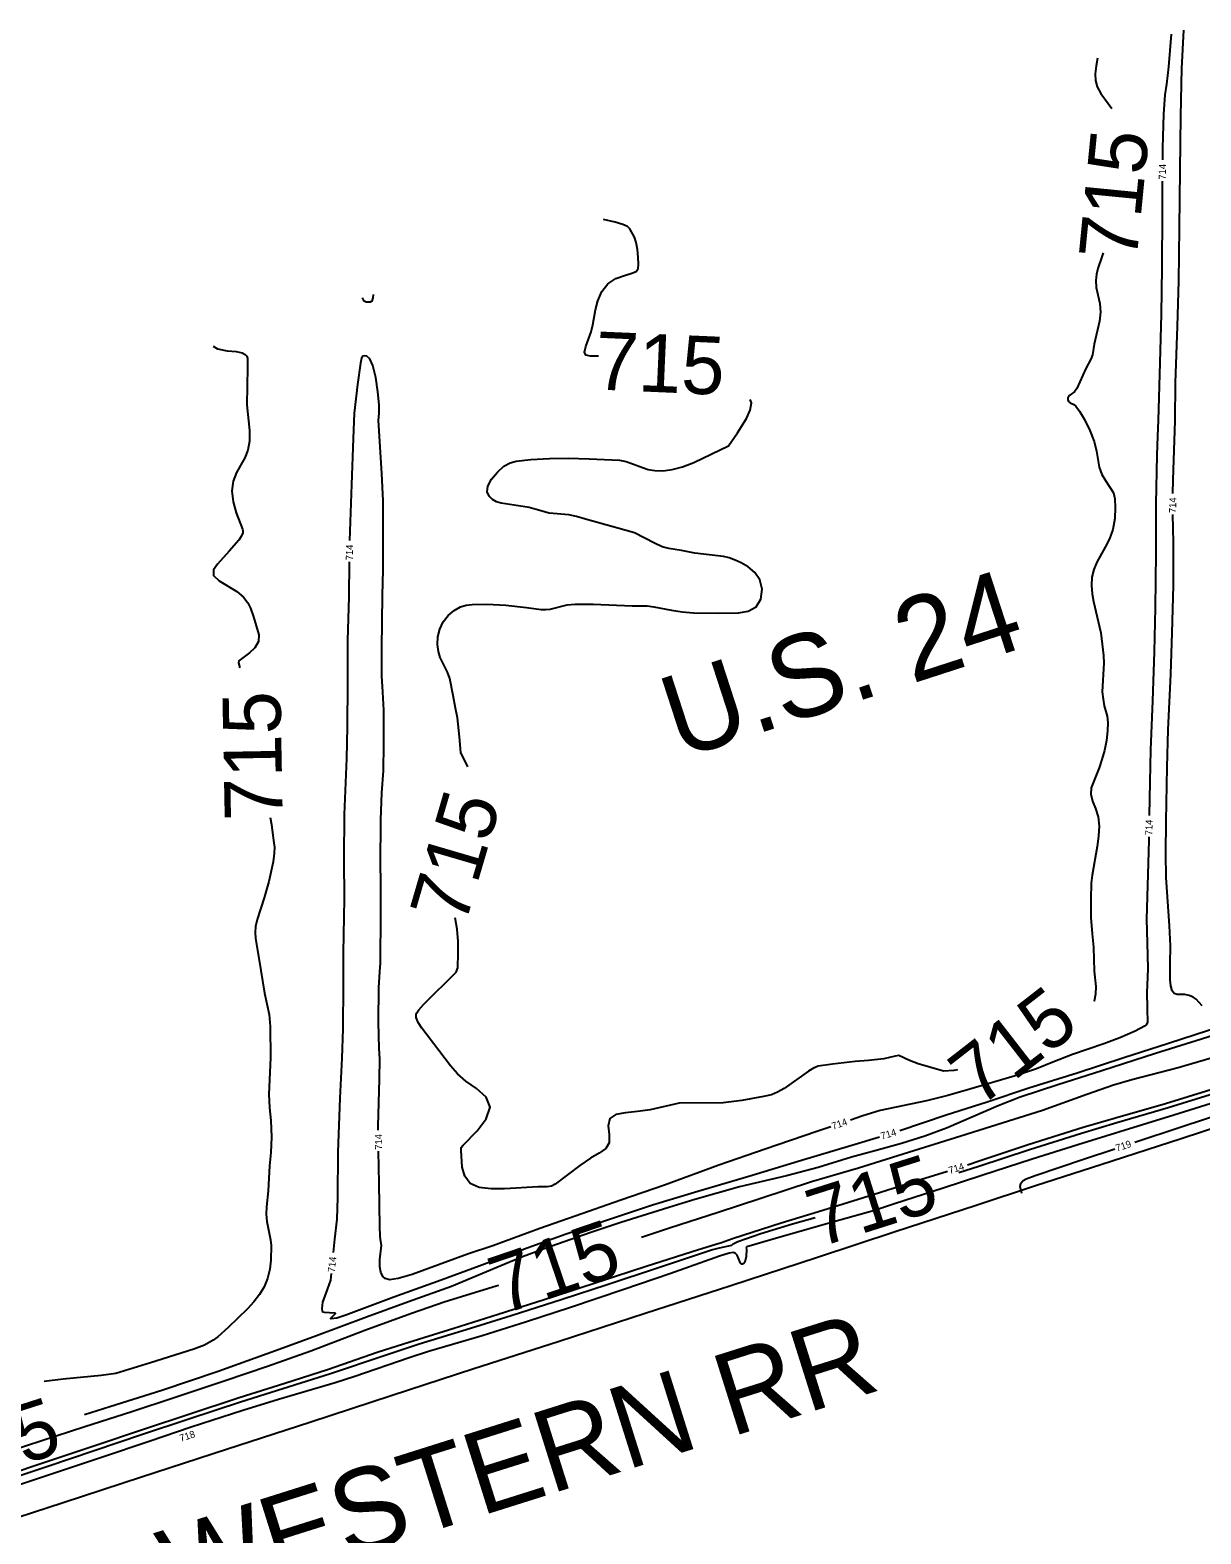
# Model space of a CAD drawing. Extents: x -468563856 to 36492962, y -306094093 to 11899197.
# Drawn here: x 1823055 to 1823721, y 531405 to 532260 of the extents above; entities that cross this region are included whole.
import ezdxf

# ---------------------------------------------------------------- set-up
doc = ezdxf.new("R2010")
doc.units = 0
for name, color, linetype in [('DT_X_Contour_Minor', 7, 'Continuous'), ('Level 14', 7, 'Continuous'), ('Level 19', 7, 'Continuous'), ('Level 40', 7, 'Continuous')]:
    doc.layers.add(name, color=color, linetype=linetype)

msp = doc.modelspace()

# ---------------------------------------------------------------- linework, layer by layer
at = {"layer": 'DT_X_Contour_Minor'}
for points in [[(1823704.79, 531997), (1823704.91, 532004.75), (1823706.02, 532038.27), (1823706.35, 532059.86), (1823707.51, 532092.13), (1823708.22, 532117.68), (1823708.55, 532147.93), (1823708.95, 532180.69), (1823709.28, 532211.54), (1823709.87, 532238.63), (1823711.02, 532260.42)], [(1823703.81, 532258.07), (1823702.34, 532239.45), (1823701.12, 532229.67), (1823700.23, 532223.63), (1823699.47, 532212.53), (1823698.89, 532193.45), (1823698.85, 532186.6)], [(1823661.94, 532244.38), (1823661.11, 532240.06), (1823660.62, 532235.61), (1823660.77, 532231.7), (1823661.75, 532228.09), (1823663.75, 532224.44), (1823670.18, 532215.81)], [(1823698.79, 532174.6), (1823698.77, 532172.19), (1823698.7, 532156.44), (1823698.5, 532125.16), (1823698.23, 532098.84), (1823697.46, 532071.21), (1823696.47, 532038.45), (1823696.13, 532029.55), (1823695.62, 532018.79), (1823695.08, 531991.07), (1823695.03, 531963.09), (1823694.75, 531931.89), (1823694.14, 531906.93), (1823693.2, 531879.13), (1823692.02, 531851.22), (1823691.64, 531832.98), (1823691.33, 531813.8)], [(1823378.07, 532074.94), (1823373.55, 532074.95), (1823371, 532075.63), (1823370.17, 532077.38), (1823370.85, 532080.52), (1823373.88, 532088.84), (1823374.88, 532092.86), (1823376.4, 532101.37), (1823377.8, 532106.55), (1823380.06, 532111.77), (1823383.47, 532116.17), (1823388.08, 532119.13), (1823393, 532120.93), (1823397.1, 532122.12), (1823399.56, 532123.22), (1823400.62, 532124.78), (1823400.85, 532127.35), (1823400.71, 532131.22), (1823400.29, 532135.68), (1823399.59, 532139.74), (1823398.64, 532142.67), (1823395.91, 532147.45), (1823394.63, 532148.72), (1823392.03, 532149.94), (1823387.57, 532151.13), (1823380.95, 532152.63)], [(1823665.16, 532133.78), (1823664.45, 532131.41), (1823662.11, 532124.84), (1823661.31, 532121.57), (1823660.96, 532118.05), (1823661.23, 532114.13), (1823663.18, 532104.95), (1823663.66, 532099.99), (1823663.13, 532095.01), (1823660.1, 532081.91), (1823659.03, 532075.76), (1823658.06, 532073.37), (1823655.21, 532067.93), (1823650.23, 532056.69), (1823648.76, 532054.81), (1823645.54, 532052.46), (1823645.04, 532051.37), (1823645.02, 532050.26), (1823645.53, 532049.3), (1823646.41, 532048.53), (1823648.39, 532047.58), (1823649.66, 532046.5), (1823651.62, 532043.83), (1823654.45, 532039.01), (1823657.53, 532032.84), (1823660.02, 532026.52), (1823661.35, 532020.96), (1823662.86, 532011.82), (1823664.4, 532007.81), (1823666.4, 532004.27), (1823671.02, 531997.25), (1823671.72, 531994), (1823672.03, 531988.93), (1823671.77, 531982.75), (1823670.72, 531976.52), (1823668.77, 531971.09), (1823666.28, 531966.38), (1823661.49, 531957.96), (1823659.8, 531953.79), (1823658.8, 531949.39), (1823658.56, 531944.67), (1823658.93, 531939.91), (1823659.68, 531935.46), (1823663.76, 531917.65), (1823665.32, 531904.88), (1823665.47, 531900.53), (1823664.64, 531884.2), (1823665.07, 531880.01), (1823665.76, 531876.29), (1823667.4, 531870.29), (1823667.82, 531866.7), (1823667.66, 531861.94), (1823666.97, 531856.44), (1823665.88, 531850.84), (1823664.49, 531845.69), (1823662.9, 531841.05), (1823658.33, 531829.53), (1823658.11, 531825.92), (1823659.13, 531822.07), (1823660.79, 531817.84), (1823662.23, 531813.1), (1823662.8, 531807.79), (1823662.56, 531802.1), (1823661.8, 531796.26), (1823658.82, 531779.96), (1823658.35, 531775.39), (1823658.14, 531766.33), (1823658.2, 531755.83), (1823658.86, 531746.66), (1823659.73, 531738.96), (1823660.11, 531725.35), (1823660.96, 531716.55), (1823660.86, 531712.34), (1823659.97, 531708.26), (1823659.9, 531708.08)], [(1823249.99, 532110.14), (1823249.78, 532108.25), (1823249.15, 532106.35), (1823248.28, 532105.66), (1823246.01, 532105.66), (1823244.83, 532106.32), (1823243.88, 532108.12), (1823243.88, 532108.16)], [(1823159.02, 532080.63), (1823161.48, 532079.17), (1823166.96, 532078.09), (1823172, 532077.59), (1823175.38, 532076.92), (1823177.27, 532076), (1823178.17, 532074.95), (1823178.53, 532073.73), (1823178.48, 532068.54), (1823178.12, 532047.3), (1823179.67, 532032.81), (1823179.66, 532026.77), (1823178.7, 532021.65), (1823176.94, 532017.25), (1823172.26, 532008.8), (1823170.31, 532004.01), (1823169.51, 531998.47), (1823170.28, 531992.13), (1823172, 531985.9), (1823175.58, 531976.61), (1823175.94, 531975.68), (1823175.82, 531974.66), (1823174.87, 531972.5), (1823173.49, 531970.46), (1823168.17, 531964.07), (1823161.37, 531956.83), (1823159.11, 531953.46), (1823159.21, 531950.27), (1823162.39, 531947.24), (1823172.49, 531941.19), (1823176.26, 531937.97), (1823178.7, 531934.77), (1823180.2, 531931.81), (1823181.83, 531926.73), (1823184.98, 531916.55), (1823184.73, 531912.7), (1823182.72, 531909.21), (1823179.72, 531906.29), (1823173.52, 531901.71), (1823173.46, 531900.65), (1823174.14, 531897.76)], [(1823252.9, 531635.02), (1823252.86, 531637.27), (1823253.52, 531664.04), (1823253.72, 531675.56), (1823253.32, 531681.32), (1823253.01, 531696.4), (1823253.19, 531715.84), (1823253.77, 531725.23), (1823254.14, 531729.88), (1823254.34, 531758.33), (1823254.26, 531776.84), (1823254.09, 531785.39), (1823254.33, 531811.44), (1823254.81, 531826.78), (1823255.82, 531839.18), (1823256.03, 531854.42), (1823255.99, 531873.76), (1823255.56, 531884.07), (1823254.89, 531893.23), (1823254.81, 531908.99), (1823255.19, 531938.86), (1823255.74, 531953.6), (1823255.7, 531982.74), (1823255.69, 531992.8), (1823254.88, 532008.39), (1823253, 532038.41), (1823253.48, 532042.65), (1823253.34, 532047.37), (1823252.63, 532054.67), (1823251.41, 532062.87), (1823249.83, 532069.72), (1823248.05, 532073.55), (1823246.32, 532074.98), (1823244.91, 532075.2), (1823244.01, 532075.06), (1823243.4, 532073.97), (1823242.79, 532071.01), (1823241.06, 532058.95), (1823239.26, 532042.66), (1823238.59, 532028.26), (1823237.68, 532002.08), (1823236.57, 531970.18)], [(1823303.81, 531841.54), (1823299.93, 531849.76), (1823299.13, 531858.6), (1823297.95, 531869.38), (1823296.86, 531874.97), (1823295.52, 531882.04), (1823293.56, 531891.75), (1823292.29, 531895.31), (1823288.11, 531903.7), (1823287.06, 531907.15), (1823286.55, 531911.08), (1823286.79, 531915.43), (1823287.87, 531919.88), (1823289.84, 531924.06), (1823292.69, 531927.66), (1823296.07, 531930.5), (1823299.57, 531932.47), (1823302.91, 531933.52), (1823306.31, 531933.91), (1823314.68, 531933.98), (1823325.52, 531933.51), (1823337.12, 531932.06), (1823345.45, 531930.96), (1823348.12, 531930.92), (1823350.55, 531931.27), (1823360.29, 531933.6), (1823364.79, 531934.01), (1823375.19, 531934), (1823397.27, 531933.16), (1823405.9, 531933), (1823409.64, 531932.51), (1823419.67, 531930.57), (1823425.71, 531929.68), (1823432.12, 531929.18), (1823446.62, 531928.98), (1823457.73, 531929.11), (1823463.16, 531930.02), (1823467.78, 531932.48), (1823470.48, 531936.95), (1823471.15, 531942.5), (1823469.92, 531947.88), (1823467.05, 531952.1), (1823463.23, 531955.19), (1823459.27, 531957.45), (1823455.78, 531959.11), (1823452.54, 531960.29), (1823449.15, 531961.04), (1823432.83, 531962.94), (1823425.3, 531964.57), (1823418.19, 531965.6), (1823414.28, 531966.7), (1823409.94, 531968.61), (1823398.58, 531974.62), (1823389.12, 531977.19), (1823370.66, 531982.35), (1823365.68, 531983.77), (1823361.28, 531984.75), (1823350.02, 531985.84), (1823342.75, 531987.82), (1823338.77, 531988.89), (1823330.12, 531990.3), (1823322.86, 531991.39), (1823320.14, 531992.2), (1823317.84, 531993.46), (1823315.9, 531995.33), (1823314.79, 531997.89), (1823315.12, 532001.19), (1823317.25, 532005.14), (1823320.61, 532009.12), (1823324.36, 532012.39), (1823327.88, 532014.39), (1823331.36, 532015.4), (1823339.73, 532016.31), (1823350.2, 532016.91), (1823360.95, 532017.06), (1823372.74, 532016.71), (1823390.15, 532015.89), (1823393.93, 532015.13), (1823400.1, 532012.92), (1823403.12, 532011.71), (1823406.43, 532010.67), (1823410.26, 532010), (1823414.8, 532009.9), (1823420.04, 532010.55), (1823425.96, 532012.11), (1823432.39, 532014.62), (1823452.08, 532023.95), (1823457.13, 532031.4), (1823462.31, 532039.64), (1823464.47, 532044.26), (1823465.14, 532048.46), (1823464.31, 532050.43)], [(1823721.45, 531705.71), (1823718.09, 531709.48), (1823716.29, 531710.54), (1823714.05, 531711.46), (1823711.66, 531712), (1823707.29, 531712.02), (1823705.59, 531712.6), (1823704.35, 531714.25), (1823703.55, 531716.93), (1823703.17, 531720.48), (1823703.3, 531729.45), (1823703.42, 531739.71), (1823702.85, 531751.07), (1823701.04, 531778.61), (1823700.72, 531792.26), (1823701.04, 531810.7), (1823701.51, 531841.28), (1823702.18, 531862.5), (1823703.66, 531894.16), (1823704.39, 531917.81), (1823705.13, 531944.7), (1823705.08, 531969.07), (1823704.7, 531985)], [(1823236.4, 531958.18), (1823236.21, 531938.14), (1823235.43, 531913.39), (1823235.32, 531888.76), (1823235.27, 531864.3), (1823234.84, 531846.28), (1823233.44, 531814.34), (1823233.36, 531788.95), (1823233.47, 531766.57), (1823232.98, 531735.78), (1823232.82, 531717.55), (1823232.74, 531692.54), (1823232.21, 531675.88), (1823231, 531653.19), (1823229.96, 531622.39), (1823229.6, 531596.69), (1823229.26, 531584.4), (1823228.03, 531572.93), (1823227.26, 531565.34)], [(1823191.32, 531812.71), (1823192.17, 531808.8), (1823192.88, 531802.47), (1823193.46, 531798.27), (1823193.79, 531795.84), (1823193.74, 531792.38), (1823193.08, 531787.54), (1823190.63, 531776.34), (1823188, 531767.13), (1823183.99, 531754.64), (1823183.14, 531750.81), (1823182.87, 531747.4), (1823183.09, 531744.05), (1823186.06, 531725.75), (1823188.2, 531712.76), (1823190.78, 531700.7), (1823191.32, 531693.84), (1823191.51, 531676.12), (1823190.55, 531655.47), (1823191.06, 531647.65), (1823191.84, 531640.5), (1823192.21, 531631), (1823191.81, 531622.26), (1823191.03, 531614.67), (1823190.23, 531600.45), (1823189.23, 531591.35), (1823189.1, 531587.11), (1823189.55, 531583.03), (1823191.65, 531572.54), (1823191.9, 531569.35), (1823191.72, 531561.02), (1823191.13, 531555.88), (1823189.94, 531550.7), (1823188, 531545.89), (1823185.37, 531541.46), (1823182.16, 531537.3), (1823178.53, 531533.35), (1823167.54, 531522.8), (1823161.54, 531517.43), (1823158.89, 531515.48), (1823154.05, 531512.78), (1823147.97, 531510.52), (1823123.32, 531502.69), (1823103.59, 531496.7), (1823095.33, 531495.43), (1823073.65, 531493.4), (1823062.79, 531492.15)], [(1823691.13, 531801.8), (1823691.09, 531799.67), (1823690.32, 531774.1), (1823689.89, 531754.89), (1823690.23, 531741.49), (1823690.63, 531726.88), (1823690.14, 531717.45), (1823689.92, 531713.36), (1823690.12, 531704.05), (1823690.31, 531696.19), (1823689.7, 531694.77), (1823688.72, 531694.03), (1823683.38, 531691.29), (1823674.64, 531687.39), (1823665.63, 531684.07), (1823647.64, 531677.95), (1823636.48, 531673.61), (1823627.33, 531669.83), (1823616.45, 531666.23), (1823589.39, 531658.21), (1823576.87, 531654.6), (1823564.75, 531651.67), (1823538.32, 531646.23), (1823528.45, 531643.08), (1823521.54, 531640.72)], [(1823583.08, 531610.8), (1823594.37, 531614.4), (1823623.25, 531623.96), (1823652.75, 531633.25), (1823672.99, 531639.28), (1823702.13, 531647.92), (1823725.93, 531655.23), (1823754.43, 531664.04), (1823782.25, 531673.11), (1823812.54, 531682.93), (1823841.29, 531692.45), (1823868.78, 531701.42), (1823898.18, 531710.9), (1823910.33, 531715.09), (1823939.28, 531725.57), (1823959.03, 531732.51), (1823975.7, 531738.36), (1823980.58, 531739.43), (1824000.39, 531745.51), (1824021.94, 531752.61), (1824055.92, 531764.58), (1824062.87, 531767.11)], [(1823582.33, 531669.19), (1823580.18, 531668.94), (1823574.34, 531668.57), (1823559.94, 531672.76), (1823554.95, 531674.53), (1823548.87, 531677.41), (1823546.9, 531677.07), (1823540.47, 531675.49), (1823531.62, 531674.58), (1823524.17, 531673.91), (1823511.28, 531672.46), (1823502.99, 531671.29), (1823500.46, 531670.29), (1823497.51, 531668.41), (1823483.7, 531658.65), (1823479.99, 531656.48), (1823476.46, 531655.09), (1823472.05, 531654.02), (1823459.72, 531651.89), (1823449.11, 531650.48), (1823423.95, 531650.25), (1823407.5, 531646.58), (1823400.39, 531645.49), (1823393.57, 531644.86), (1823387.96, 531643.93), (1823384.5, 531641.68), (1823383.68, 531637.51), (1823384.17, 531632.4), (1823384.19, 531627.74), (1823382.31, 531624.48), (1823378.6, 531621.93), (1823373.52, 531618.98), (1823367.59, 531614.88), (1823353.41, 531604.2), (1823351.43, 531603.14), (1823348.92, 531602.76), (1823343.82, 531602.66), (1823324.73, 531601.64), (1823317.18, 531601.57), (1823310.34, 531602.36), (1823305.08, 531604.68), (1823302.03, 531608.88), (1823300.66, 531613.95), (1823299.95, 531623.48), (1823300.1, 531625.07), (1823301.19, 531626.37), (1823309.16, 531634.65), (1823314.2, 531641.33), (1823316.49, 531648.06), (1823314.15, 531653.78), (1823308.73, 531658.59), (1823302.68, 531662.89), (1823297.86, 531667.05), (1823293.94, 531671.46), (1823277.63, 531692.92), (1823275.58, 531696.14), (1823274.5, 531699.05), (1823274.5, 531700.88), (1823274.77, 531701.73), (1823275.93, 531703.4), (1823278.8, 531706.52), (1823297.12, 531724.8), (1823298.1, 531727.2), (1823298.35, 531735.62), (1823298.26, 531742.18), (1823297.71, 531749.15), (1823296.55, 531755.61)], [(1823683.11, 531628.14), (1823709.45, 531636.8), (1823736.68, 531645.7), (1823765.62, 531655.27), (1823795.33, 531664.93), (1823824.19, 531674.26), (1823856.47, 531684.61), (1823883.31, 531693.48), (1823904.53, 531700.65), (1823925.53, 531708.47), (1823941.77, 531714.29), (1823969.1, 531723.78), (1823992.51, 531731.76), (1823992.8, 531731.86)], [(1823741.04, 531692.87), (1823718.08, 531685.81), (1823694.93, 531678.56), (1823664.36, 531668.64), (1823639.45, 531660.71), (1823617.87, 531653.65), (1823605.47, 531648.8), (1823576.03, 531636), (1823563.68, 531631.52), (1823550.54, 531627.31), (1823536.01, 531623.38), (1823522, 531619.7), (1823503.15, 531613.64), (1823485.03, 531609.02), (1823458.27, 531602.76), (1823432.96, 531595.49), (1823418.16, 531591), (1823390.92, 531582.37), (1823373.85, 531576.69), (1823347.26, 531567.51), (1823334.88, 531562.99), (1823320.3, 531556.92), (1823294.52, 531546.06), (1823270.14, 531537.32), (1823246.11, 531528.55), (1823217.72, 531517.98), (1823194.49, 531509.41), (1823161.84, 531497.74), (1823129.79, 531486.86), (1823100.18, 531477.58), (1823085.84, 531473.02)], [(1823549.48, 531634.79), (1823575.92, 531643.74), (1823599.19, 531651.16), (1823622.9, 531658.95), (1823650.39, 531667.51), (1823676.98, 531676.24), (1823702.23, 531684.46), (1823732.69, 531694.25)], [(1823402.67, 531574.19), (1823418.5, 531579.46), (1823446.24, 531588.36), (1823470.52, 531596.33), (1823499.27, 531605.78), (1823526.05, 531613.63), (1823551.44, 531621.41), (1823584.15, 531631.83), (1823601.12, 531637.03), (1823630.66, 531646.33), (1823655.85, 531655.37), (1823671, 531660.71), (1823681.44, 531663.7), (1823707.77, 531670.66), (1823726.66, 531676.16)], [(1823588.03, 531615.33), (1823595.29, 531617.65), (1823622.48, 531626.73), (1823653.75, 531636.58), (1823672.16, 531641.94), (1823700.56, 531650.16), (1823726.33, 531658.02)], [(1823732.63, 531651.98), (1823705.27, 531643.44), (1823674.66, 531633.95), (1823650.75, 531626.59), (1823624.78, 531618.41), (1823596.17, 531609.12), (1823574.14, 531602.01), (1823546.55, 531592.98), (1823535.09, 531589.37), (1823507.23, 531581.44), (1823476.06, 531572.67), (1823462.51, 531568.67), (1823462.18, 531568.21), (1823462.36, 531567.12), (1823462.08, 531563.13), (1823461.35, 531559.99), (1823460.74, 531559.08), (1823460.07, 531558.7), (1823459.44, 531558.82), (1823458.95, 531559.38), (1823456.91, 531563.96), (1823456.12, 531564.91), (1823454.98, 531565.36), (1823452.36, 531564.94), (1823446.95, 531563.27), (1823418.62, 531553.31), (1823392.63, 531544.37), (1823362.29, 531534.04), (1823337.23, 531526), (1823311.97, 531518.07), (1823281.48, 531509.06), (1823270.39, 531505.48), (1823239.55, 531494.95), (1823228.3, 531491.37), (1823196.13, 531481.89), (1823175.9, 531475.5), (1823146.52, 531466.02), (1823122.49, 531457.9), (1823095.56, 531448.81), (1823068.15, 531439.7), (1823041.39, 531430.8)], [(1823510.19, 531636.83), (1823502.37, 531634.15), (1823473.01, 531624.13), (1823446.59, 531615.02), (1823415.7, 531603.77), (1823390.85, 531595.12), (1823364.9, 531586.14), (1823344.69, 531579.1), (1823318.06, 531569.25), (1823304.24, 531564.59), (1823296.36, 531561.89), (1823272.08, 531552.97), (1823264.15, 531550.59), (1823259.21, 531549.93), (1823256.71, 531550.55), (1823255.55, 531551.75), (1823254.29, 531554.16), (1823253.71, 531557.17), (1823253.79, 531561.5), (1823254.7, 531569.39), (1823254.22, 531572.96), (1823253.91, 531574.63), (1823253.78, 531580.28), (1823253.4, 531604.82), (1823253.1, 531623.03)], [(1823226.05, 531553.4), (1823225.67, 531549.63), (1823223.75, 531544.38), (1823221.15, 531537.13), (1823220.78, 531533.32), (1823220.91, 531532.27), (1823221.35, 531531.71), (1823222.17, 531531.51), (1823228.13, 531531.09), (1823228.52, 531530.74), (1823228.2, 531530.27), (1823225.64, 531527.92), (1823226.1, 531527.79), (1823229.22, 531528.28), (1823234.4, 531530.01), (1823261.66, 531540.24), (1823288.61, 531549.8), (1823310.19, 531557.78), (1823337.51, 531568.02), (1823359.8, 531576.06), (1823386.58, 531585.17), (1823408.85, 531592.53), (1823434.6, 531600.2), (1823463.62, 531608.77), (1823491.64, 531617.26), (1823522.12, 531626.48), (1823538.01, 531631.24)], [(1823618.93, 531599.03), (1823617.93, 531602.89), (1823618.29, 531604.87), (1823619.6, 531606.35), (1823621.42, 531607.36), (1823626.42, 531609.14), (1823654.01, 531618.54), (1823671.71, 531624.39)], [(1823040.12, 531438.43), (1823065.6, 531446.94), (1823089.93, 531455.09), (1823120.45, 531465.39), (1823144.48, 531473.36), (1823173.71, 531482.93), (1823199.82, 531491.16), (1823224.53, 531499.12), (1823252.17, 531508.66), (1823267.14, 531513.57), (1823295.76, 531522.4), (1823320.99, 531530.34), (1823351.88, 531540.24), (1823378.47, 531548.9), (1823405.16, 531557.61), (1823435.06, 531567.17), (1823446.74, 531570.8), (1823448.02, 531571.09), (1823454.29, 531573.36), (1823482.04, 531582.3), (1823503.2, 531588.73), (1823534.3, 531598.39), (1823561.36, 531606.83), (1823576.6, 531611.69)], [(1823040.41, 531435.84), (1823064.29, 531443.8), (1823091.81, 531452.99), (1823118.31, 531461.94), (1823145.16, 531470.91), (1823174.44, 531480.45), (1823198.59, 531488.07), (1823225.79, 531496.54), (1823256.23, 531506.92), (1823276.21, 531513.39), (1823305.35, 531522.29), (1823328.52, 531529.57), (1823357.45, 531538.86), (1823383.04, 531547.24), (1823412.35, 531556.94), (1823442.39, 531566.83), (1823446.86, 531568.14), (1823453.88, 531569.59), (1823454.64, 531570.3), (1823457.4, 531571.64), (1823470.55, 531576.18), (1823488.54, 531581.65), (1823501.36, 531585.34)], [(1822864.84, 531394.23), (1822865.51, 531394.46), (1822895.7, 531404.69), (1822921.62, 531413.35), (1822945.29, 531420.57), (1822967.95, 531428.03), (1823001.63, 531439.54), (1823033.39, 531449.42), (1823061.54, 531458.59), (1823085.97, 531466.51), (1823112.8, 531475.09), (1823136.87, 531483.01), (1823165.87, 531492.65), (1823189.79, 531500.79), (1823214.61, 531509.5), (1823245.21, 531521.28), (1823271.75, 531530.93), (1823290.9, 531537.63), (1823319.88, 531546.38), (1823321.53, 531546.92)]]:
    msp.add_lwpolyline(points, dxfattribs=at)
at = {"layer": 'Level 14'}
msp.add_lwpolyline([(1823905.32, 531693.73), (1823856.68, 531677.81), (1823808.23, 531662.16), (1823759.17, 531646.3), (1823709.45, 531630.09), (1823663.76, 531615.33), (1823626.69, 531603.28), (1823592.93, 531592.11), (1823546.85, 531577.13), (1823502.6, 531562.57), (1823453.47, 531546.49), (1823404.63, 531530.76), (1823355.72, 531514.87), (1823306.7, 531499.05), (1823260.73, 531484.09), (1823213.94, 531468.77), (1823166.5, 531453.32), (1823118.2, 531437.61), (1823073.63, 531423.06), (1823030.5, 531409.05)], dxfattribs=at)

# ---------------------------------------------------------------- texts
at = {"layer": 'Level 19'}
for s, height, rotation, p in [('715', 33, 84.40241, (1823684.06, 532128.63)), ('714', 4, 89.70227, (1823700.79, 532175.38)), ('715', 33, 357.52566, (1823375.67, 532056.13)), ('714', 4, 89.15796, (1823706.63, 531985.76)), ('714', 4, 89.44444, (1823238.41, 531958.95)), ('715', 33, 91.07164, (1823198.58, 531811.13)), ('715', 33, 73.67698, (1823302.09, 531750.6)), ('714', 4, 89.06056, (1823693.14, 531802.56)), ('715', 33, 37.82668, (1823594.73, 531647.44)), ('714', 4, 18.89615, (1823511.58, 531635.19)), ('714', 4, 90.94559, (1823255.08, 531623.85)), ('714', 4, 16.69026, (1823539.34, 531629.55)), ('719', 4, 18.28308, (1823673.04, 531622.72)), ('715', 33, 17.61272, (1823503.35, 531568.15)), ('714', 4, 17.68721, (1823577.96, 531610.02)), ('715', 33, 18.80448, (1823323.38, 531529.87)), ('714', 4, 84.20761, (1823228.12, 531553.98)), ('715', 33, 17.73877, (1823004.42, 531429.92)), ('718', 4, 17.9565, (1823140.6, 531457.76))]:
    msp.add_text(s, height=height, rotation=rotation, dxfattribs=at).set_placement(p)
at = {"layer": 'Level 40'}
for s, rotation, p in [('U.S. 24', 17.98637, (1823423.95, 531845.73)), ('MAUMEE & WESTERN RR', 17.51707, (1822803.63, 531255.29))]:
    msp.add_text(s, height=46.8, rotation=rotation, dxfattribs=at).set_placement(p)

doc.saveas('drawing.dxf')
